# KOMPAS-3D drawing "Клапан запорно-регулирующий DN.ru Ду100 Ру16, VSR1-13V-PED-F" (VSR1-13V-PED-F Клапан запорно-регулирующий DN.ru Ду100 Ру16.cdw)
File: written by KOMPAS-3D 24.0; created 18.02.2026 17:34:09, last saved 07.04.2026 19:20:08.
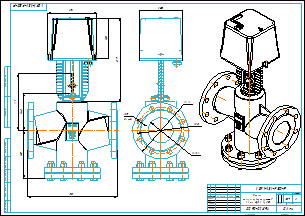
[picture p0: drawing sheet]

Document properties: Автор: R2D2; Форматы листов документа: A2; Полное имя файла: VSR1-13V-PED-F Клапан запорно-регулирующий DN.ru Ду100 Ру16.m3d; Масса: 33.7; Наименование: Клапан запорно-регулирующий DN.ru Ду100 Ру16; Количество листов документа: 1; Примечание: D090-02894

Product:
- Part/product: Клапан запорно-регулирующий DN.ru Ду100 Ру16  | designation VSR1-13V-PED-F
    Масса: 33.7
    Раздел спецификации: Прочие изделия
    Примечание: D090-02894

Views: Вид 1, Спереди
Referenced files in E:\Работа\Зайцев\Солянка\VSR1-13V-PED-F Клапан запорно-регулирующий DN.ru\DN15\DN15 Kv0.16\: VSR1-13V-PED-F Клапан запорно-регулирующий DN.ru Ду15 Ру16.m3d
Referenced files in E:\Работа\Зайцев\Солянка\VSR1-13V-PED-F Клапан запорно-регулирующий DN.ru\DN100\: VSR1-13V-PED-F Клапан запорно-регулирующий DN.ru Ду100 Ру16.m3d
Referenced files in E:\Работа\Зайцев\Для компаса\: чертеж DN.ru А3.cdt
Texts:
  Линейный размер
  VSR1-13V-PED-F
  чертеж DN.ru А3.cdt
  Клапан
  запорно-регулирующий
  DN.ru Ду100 Ру16
  Клапан запорно-регулирующий DN.ru Ду100 Ру16
  VSR1-13V-PED-F Клапан запорно-регулирующий DN.ru Ду100 Ру16
Dimensions and other numbers on the sheet: 0; 3; 2; 4; 350; 186; 146; 221; 190; 327; 158; 1:2; 1; 33,7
